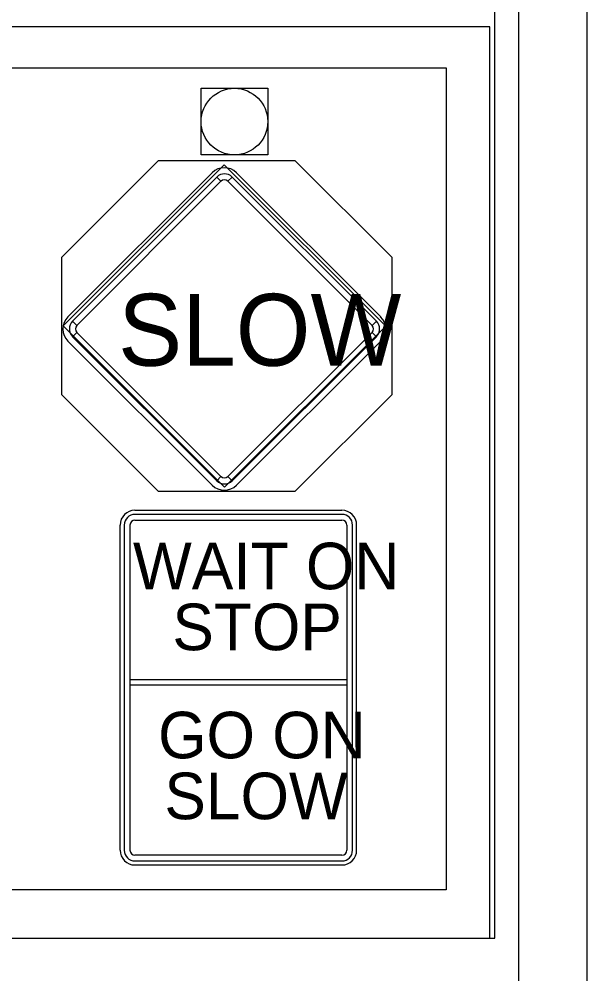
# Model space of a CAD drawing. Extents: x 21.7 to 29.1, y 5.9 to 16.2.
# Drawn here: x 28.39 to 29.094, y 12.972 to 14.157 of the extents above; entities that cross this region are included whole.
import ezdxf

# ---------------------------------------------------------------- set-up
doc = ezdxf.new("R2010")
doc.units = 0
for name, color, linetype in [('BORD-LINE', 7, 'Continuous'), ('DETL-LINE', 7, 'Continuous'), ('USER-BORD', 7, 'Continuous')]:
    doc.layers.add(name, color=color, linetype=linetype)

msp = doc.modelspace()

# ---------------------------------------------------------------- linework, layer by layer
at = {"layer": 'BORD-LINE'}
for p, q in [((28.5332, 13.5474), (28.7898, 13.5474)), ((28.5148, 13.1258), (28.5148, 13.5291)), ((28.8081, 13.1258), (28.8081, 13.5291)), ((28.5332, 13.1075), (28.7898, 13.1075))]:
    msp.add_line(p, q, dxfattribs=at)
msp.add_lwpolyline([(21.7194, 16.2106), (29.0936, 16.2106), (29.0936, 5.8575), (21.7194, 5.8575)], close=True, dxfattribs=at)
for points in [[(28.7898, 13.5423), (28.5332, 13.5423)], [(28.5199, 13.5291), (28.5199, 13.4668)], [(28.5271, 13.4668), (28.5271, 13.5291)], [(28.5332, 13.5352), (28.7898, 13.5352)], [(28.7959, 13.5291), (28.7959, 13.1258)], [(28.8031, 13.1258), (28.8031, 13.5291)], [(28.5199, 13.4668), (28.5199, 13.4518), (28.5199, 13.1258)], [(28.5271, 13.1258), (28.5271, 13.4668)], [(28.7898, 13.1197), (28.5332, 13.1197)], [(28.5332, 13.1126), (28.7898, 13.1126)]]:
    msp.add_lwpolyline(points, dxfattribs=at)
for centre, radius, start, end in [((28.5332, 13.5291), 0.0183, 90, 180), ((28.5332, 13.5291), 0.0132, 90, 180), ((28.7898, 13.5291), 0.0183, 0, 90), ((28.7898, 13.5291), 0.0132, 0, 90), ((28.5332, 13.5291), 0.00611, 90, 180), ((28.7898, 13.5291), 0.00611, 0, 90), ((28.5332, 13.1258), 0.0183, 180, 270), ((28.5332, 13.1258), 0.0132, 180, 270), ((28.5332, 13.1258), 0.00611, 180, 270), ((28.7898, 13.1258), 0.0183, 270, 360), ((28.7898, 13.1258), 0.0132, 270, 360), ((28.7898, 13.1258), 0.00611, 270, 360)]:
    msp.add_arc(centre, radius, start, end, dxfattribs=at)
at = {"layer": 'DETL-LINE'}
for points in [[(25.7831, 11.5962), (29.0092, 11.5962), (29.0092, 14.3652), (25.7831, 14.3652)], [(25.8041, 13.0169), (28.9793, 13.0169), (28.9793, 14.3329), (25.8041, 14.3329)], [(28.9732, 14.1469), (25.8041, 14.1469), (25.8041, 13.0169), (28.9732, 13.0169)], [(27.6979, 14.0964), (28.9189, 14.0964), (28.9189, 13.0769), (27.6979, 13.0769)], [(28.6153, 14.0708), (28.6978, 14.0708), (28.6978, 13.9882), (28.6153, 13.9882)], [(28.5271, 13.3306), (28.5271, 13.3377), (28.7959, 13.3377), (28.7959, 13.3306)]]:
    msp.add_lwpolyline(points, close=True, dxfattribs=at)
msp.add_circle((28.6566, 14.0295), 0.0413, dxfattribs=at)
at = {"layer": 'USER-BORD'}
for p, q in [((28.45, 13.7872), (28.629, 13.9661)), ((28.838, 13.7872), (28.6591, 13.9661)), ((28.4557, 13.7819), (28.6346, 13.9608)), ((28.6399, 13.9555), (28.461, 13.7766)), ((28.6346, 13.9608), (28.6399, 13.9555)), ((28.6346, 13.9608), (28.6399, 13.9555)), ((28.6485, 13.9555), (28.6538, 13.9608)), ((28.6485, 13.9555), (28.6538, 13.9608)), ((28.8274, 13.7766), (28.6485, 13.9555)), ((28.6538, 13.9608), (28.8327, 13.7819)), ((28.461, 13.7766), (28.4557, 13.7819)), ((28.4557, 13.7819), (28.461, 13.7766)), ((28.8327, 13.7819), (28.8274, 13.7766)), ((28.8327, 13.7819), (28.8274, 13.7766)), ((28.461, 13.768), (28.4557, 13.7627)), ((28.4557, 13.7627), (28.6346, 13.5841)), ((28.6399, 13.5894), (28.461, 13.768)), ((28.6485, 13.5894), (28.8274, 13.768)), ((28.8327, 13.7627), (28.6538, 13.5841)), ((28.8274, 13.768), (28.8327, 13.7627)), ((28.8274, 13.768), (28.8327, 13.7627)), ((28.45, 13.7574), (28.629, 13.5788)), ((28.838, 13.7574), (28.6591, 13.5788)), ((28.6346, 13.5841), (28.6399, 13.5894)), ((28.6346, 13.5841), (28.6399, 13.5894)), ((28.6538, 13.5841), (28.6485, 13.5894)), ((28.6485, 13.5894), (28.6538, 13.5841))]:
    msp.add_line(p, q, dxfattribs=at)
for points in [[(28.7319, 13.5711), (28.852, 13.6911), (28.852, 13.8609), (28.7319, 13.981), (28.5621, 13.981), (28.4421, 13.8609), (28.4421, 13.6911), (28.5621, 13.5711)], [(28.644, 13.9761), (28.8441, 13.776), (28.6442, 13.576), (28.4441, 13.7761)]]:
    msp.add_lwpolyline(points, close=True, dxfattribs=at)
for centre, radius, start, end in [((28.644, 13.951), 0.0213, 45, 135), ((28.6442, 13.9512), 0.0135, 45, 135), ((28.6442, 13.9512), 0.00602, 45, 135), ((28.4652, 13.7722), 0.0213, 134.9987, 224.9987), ((28.8228, 13.7722), 0.0213, 315.0013, 45.0013), ((28.4654, 13.7724), 0.0135, 135, 225), ((28.4654, 13.7724), 0.00602, 135, 225), ((28.823, 13.7724), 0.00602, 315, 45), ((28.823, 13.7724), 0.0135, 315, 45), ((28.6442, 13.5936), 0.0135, 225, 315), ((28.6442, 13.5936), 0.00602, 225, 315), ((28.644, 13.5937), 0.0213, 225, 315)]:
    msp.add_arc(centre, radius, start, end, dxfattribs=at)

# ---------------------------------------------------------------- texts
for s, height, p in [('SLOW', 0.08918, (28.5123, 13.7267)), ('WAIT ON', 0.05774, (28.5308, 13.4495)), ('STOP', 0.05774, (28.5796, 13.3739)), ('GO ON', 0.05774, (28.5619, 13.2398)), ('SLOW', 0.05774, (28.5697, 13.1643))]:
    msp.add_text(s, height=height, dxfattribs=at).set_placement(p)

doc.saveas('drawing.dxf')
